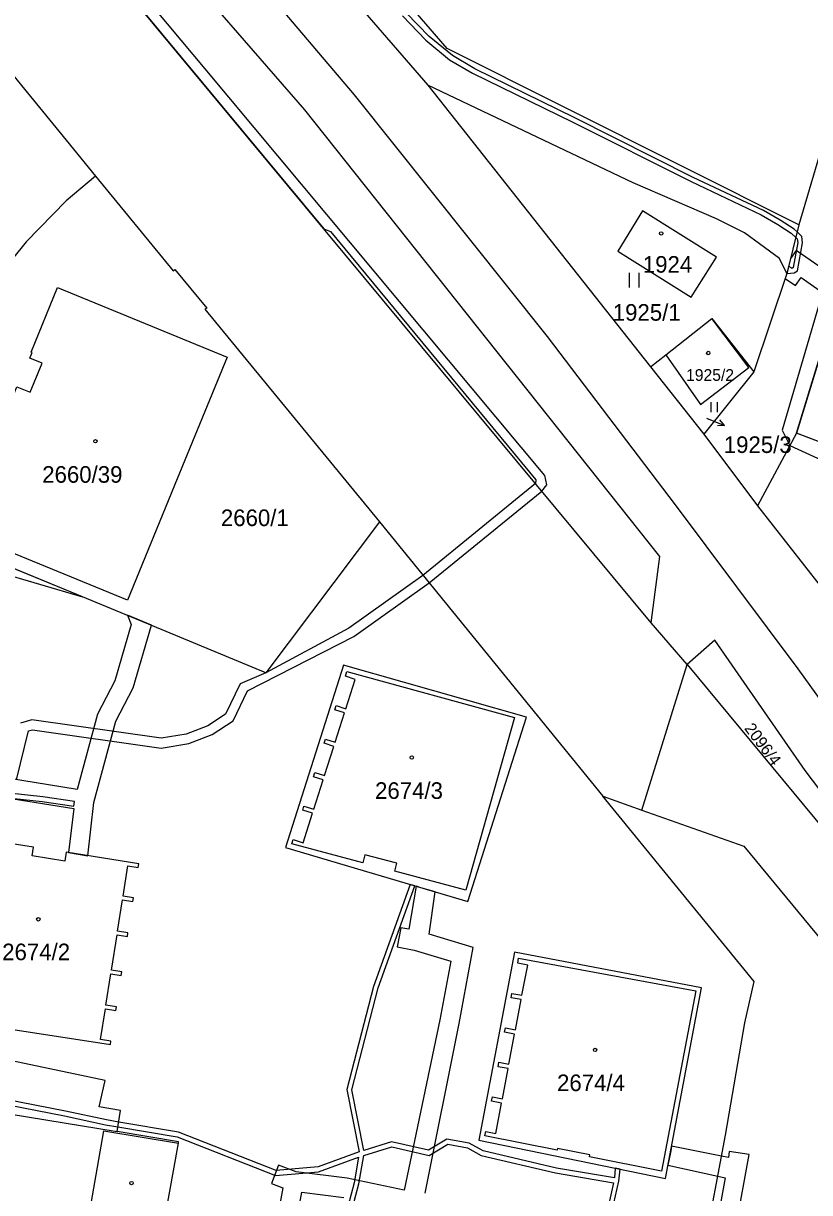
# Model space of a CAD drawing. Extents: x -756746 to -753363, y -1166406 to -1161727.
# Drawn here: x -755238.8 to -755158.3, y -1165086.9 to -1164967.1 of the extents above; entities that cross this region are included whole.
import ezdxf

# ---------------------------------------------------------------- set-up
doc = ezdxf.new("R2010")
doc.units = 0
for name, color, linetype in [('Hranice parcel', 7, 'Continuous'), ('Parcelní čísla', 7, 'Continuous'), ('Pop  PČ popisy', 7, 'Continuous'), ('Poz předměty', 7, 'Continuous'), ('Vnitřní kresba', 7, 'Continuous'), ('Věcná břemena k části', 7, 'Continuous'), ('Značky budov', 7, 'Continuous'), ('Značky kultur', 7, 'Continuous')]:
    doc.layers.add(name, color=color, linetype=linetype)

msp = doc.modelspace()

# ---------------------------------------------------------------- linework, layer by layer
at = {"layer": 'Hranice parcel'}
for p, q in [((-755232.98, -1164932.34), (-755197.4, -1164973.47)), ((-755150.26, -1164956.7), (-755159.39, -1164987.78)), ((-755197.4, -1164973.47), (-755174.57, -1165002.34)), ((-755159.39, -1164987.78), (-755160.61, -1164992.76)), ((-755160.61, -1164992.76), (-755163.99, -1165002.83)), ((-755154.6, -1164992.66), (-755159.64, -1165009.12)), ((-755173.02, -1165001.11), (-755168.29, -1164997.38)), ((-755168.29, -1164997.38), (-755163.99, -1165002.83)), ((-755174.57, -1165002.34), (-755173.02, -1165001.11)), ((-755174.57, -1165002.34), (-755169.12, -1165009.25)), ((-755163.99, -1165002.83), (-755169.12, -1165009.25)), ((-755169.12, -1165009.25), (-755163.64, -1165016.58)), ((-755159.64, -1165009.12), (-755163.64, -1165016.58)), ((-755146.3, -1165014.2), (-755159.64, -1165009.12)), ((-755163.64, -1165016.58), (-755133.33, -1165055.24)), ((-755202.36, -1165018.23), (-755179.46, -1165046.33)), ((-755170.82, -1165032.84), (-755174.51, -1165028.57)), ((-755175.48, -1165047.75), (-755170.82, -1165032.84)), ((-755170.82, -1165032.84), (-755144.59, -1165064.52)), ((-755179.46, -1165046.33), (-755175.48, -1165047.75)), ((-755225.33, -1165095.26), (-755222.94, -1165081.86))]:
    msp.add_line(p, q, dxfattribs=at)
for points in [[(-755174.51, -1165028.57), (-755173.62, -1165021.77), (-755210, -1164975.99), (-755240.66, -1164940.74), (-755264.36, -1164914.76), (-755305.85, -1164872.21)], [(-755174.51, -1165028.57), (-755239.27, -1164950.56), (-755255.53, -1164931.93), (-755293.61, -1164892.37), (-755304.73, -1164881.59)], [(-755159.39, -1164987.78), (-755195.43, -1164969.72), (-755209.4, -1164953.49)], [(-755243, -1164968.67), (-755235.2, -1164978.19), (-755231.43, -1164982.79)], [(-755160.61, -1164992.76), (-755161.38, -1164991.25), (-755164.97, -1164988.59), (-755167.82, -1164987.16), (-755176.37, -1164983.48), (-755197.4, -1164973.47)], [(-755231.43, -1164982.79), (-755234.45, -1164985.34), (-755238.55, -1164989.54), (-755241.2, -1164992.83), (-755243.99, -1164996.98), (-755245.9, -1165000.12), (-755247.84, -1165004.11), (-755249.68, -1165008.88), (-755251.02, -1165013.51)], [(-755231.43, -1164982.79), (-755223.48, -1164992.49), (-755223.3, -1164992.35), (-755220.03, -1164996.34), (-755220.24, -1164996.41), (-755202.36, -1165018.23)], [(-755175.39, -1164986.34), (-755177.93, -1164990.48), (-755170.41, -1164995.19), (-755167.83, -1164991.09), (-755175.39, -1164986.34)], [(-755228.17, -1165026.24), (-755245.56, -1165019.09), (-755242.86, -1165012.59), (-755242.76, -1165012.63), (-755242.52, -1165011.99), (-755241.25, -1165012.48), (-755240, -1165009.51), (-755241.38, -1165008.93), (-755239.5, -1165004.37), (-755238.12, -1165004.94), (-755236.91, -1165001.96), (-755238.17, -1165001.45), (-755237.91, -1165000.87), (-755238.01, -1165000.83), (-755235.33, -1164994.21), (-755217.94, -1165001.36), (-755223.06, -1165013.8), (-755228.17, -1165026.24)], [(-755173.02, -1165001.11), (-755169.47, -1165006.18), (-755164.5, -1165002.42), (-755168.29, -1164997.38)], [(-755228.38, -1165027.7), (-755232.75, -1165025.91), (-755252.01, -1165017.99)], [(-755202.36, -1165018.23), (-755214, -1165033.67), (-755228.38, -1165027.7)], [(-755144.59, -1165064.52), (-755150.03, -1165055.18), (-755158.73, -1165043.7), (-755167.99, -1165030.34), (-755170.82, -1165032.84)], [(-755187.29, -1165038.23), (-755206.02, -1165032.89), (-755211.96, -1165051.58), (-755193.28, -1165057.13), (-755187.29, -1165038.23)], [(-755195.18, -1165232.73), (-755194.72, -1165230.22), (-755190.08, -1165204.4), (-755187.88, -1165193.31), (-755185.72, -1165181.35), (-755183.4, -1165169.62), (-755181.35, -1165158.07), (-755178.5, -1165145.99), (-755176.9, -1165134.25), (-755174.82, -1165122.5), (-755171.34, -1165104.62), (-755169.11, -1165092.87), (-755166.91, -1165081.07), (-755164.91, -1165069.54), (-755163.98, -1165065.31), (-755179.46, -1165046.33)], [(-755175.48, -1165047.75), (-755165.04, -1165051.46), (-755150.8, -1165068.69)], [(-755240.75, -1165070.08), (-755229.91, -1165071.78), (-755229.85, -1165071.42), (-755230.91, -1165071.25), (-755230.42, -1165068.1), (-755229.36, -1165068.27), (-755229.3, -1165067.92), (-755230.36, -1165067.75), (-755229.85, -1165064.51), (-755228.79, -1165064.68), (-755228.74, -1165064.31), (-755229.79, -1165064.15), (-755229.23, -1165060.53), (-755228.17, -1165060.7), (-755228.11, -1165060.33), (-755229.17, -1165060.17), (-755228.66, -1165056.94), (-755227.6, -1165057.1), (-755227.54, -1165056.73), (-755228.6, -1165056.56), (-755228.11, -1165053.45), (-755227.05, -1165053.62), (-755227, -1165053.25), (-755234.44, -1165052.07), (-755234.59, -1165052.97), (-755237.93, -1165052.44), (-755237.78, -1165051.54), (-755245.22, -1165050.37)], [(-755192.17, -1165081.55), (-755173.06, -1165085.49), (-755169.36, -1165065.96), (-755188.53, -1165062.31), (-755192.17, -1165081.55)], [(-755229.21, -1165080.69), (-755228.87, -1165078.51), (-755231.05, -1165078.14), (-755230.44, -1165075.45), (-755241.34, -1165073.17), (-755240.75, -1165070.08)], [(-755257.09, -1165075.73), (-755243.85, -1165078.28), (-755229.21, -1165080.69)], [(-755232.91, -1165093.94), (-755230.59, -1165080.61), (-755222.94, -1165081.86)], [(-755222.94, -1165081.86), (-755222.92, -1165081.73), (-755229.21, -1165080.69)]]:
    msp.add_lwpolyline(points, dxfattribs=at)
at = {"layer": 'Pop  PČ popisy'}
for p, q in [((-755168.85, -1165007.58), (-755166.99, -1165008.33)), ((-755166.99, -1165008.33), (-755167.73, -1165008.39)), ((-755166.99, -1165008.33), (-755167.48, -1165007.77))]:
    msp.add_line(p, q, dxfattribs=at)
at = {"layer": 'Poz předměty'}
for p, q in [((-755204.91, -1164974.48), (-755230.66, -1164944.05)), ((-755185.13, -1164999.24), (-755204.91, -1164974.48)), ((-755172.01, -1165016.47), (-755185.13, -1164999.24)), ((-755159.45, -1165033.28), (-755172.01, -1165016.47)), ((-755146.57, -1165051.26), (-755159.45, -1165033.28))]:
    msp.add_line(p, q, dxfattribs=at)
at = {"layer": 'Vnitřní kresba'}
for p, q in [((-755205.84, -1165034.04), (-755205.68, -1165033.56)), ((-755204.84, -1165034.36), (-755205.84, -1165034.04)), ((-755205.79, -1165037.36), (-755204.84, -1165034.36)), ((-755205.68, -1165033.56), (-755188.52, -1165038.26)), ((-755206.93, -1165037.47), (-755206.79, -1165037.04)), ((-755206.79, -1165037.04), (-755205.79, -1165037.36)), ((-755205.93, -1165037.79), (-755206.93, -1165037.47)), ((-755206.89, -1165040.79), (-755205.93, -1165037.79)), ((-755188.52, -1165038.26), (-755193.5, -1165055.95)), ((-755208.02, -1165040.9), (-755207.89, -1165040.48)), ((-755207.89, -1165040.48), (-755206.89, -1165040.79)), ((-755207.02, -1165041.22), (-755208.02, -1165040.9)), ((-755207.99, -1165044.21), (-755207.02, -1165041.22)), ((-755209.12, -1165044.33), (-755208.98, -1165043.89)), ((-755208.98, -1165043.89), (-755207.99, -1165044.21)), ((-755208.12, -1165044.65), (-755209.12, -1165044.33)), ((-755209.08, -1165047.65), (-755208.12, -1165044.65)), ((-755210.21, -1165047.75), (-755210.08, -1165047.33)), ((-755209.21, -1165048.07), (-755210.21, -1165047.75)), ((-755210.08, -1165047.33), (-755209.08, -1165047.65)), ((-755210.18, -1165051.09), (-755209.21, -1165048.07)), ((-755211.32, -1165051.2), (-755211.18, -1165050.77)), ((-755204.04, -1165053.14), (-755211.32, -1165051.2)), ((-755211.18, -1165050.77), (-755210.18, -1165051.09)), ((-755203.83, -1165052.34), (-755204.04, -1165053.14)), ((-755200.57, -1165053.2), (-755203.83, -1165052.34)), ((-755200.78, -1165054.01), (-755200.57, -1165053.2)), ((-755193.5, -1165055.95), (-755200.78, -1165054.01)), ((-755188.19, -1165063.43), (-755188.1, -1165062.93)), ((-755187.16, -1165063.63), (-755188.19, -1165063.43)), ((-755188.1, -1165062.93), (-755169.94, -1165066.27)), ((-755187.75, -1165066.72), (-755187.16, -1165063.63)), ((-755188.86, -1165066.97), (-755188.78, -1165066.53)), ((-755187.83, -1165067.17), (-755188.86, -1165066.97)), ((-755188.78, -1165066.53), (-755187.75, -1165066.72)), ((-755169.94, -1165066.27), (-755173.46, -1165084.74)), ((-755188.41, -1165070.26), (-755187.83, -1165067.17)), ((-755189.54, -1165070.51), (-755189.45, -1165070.07)), ((-755188.5, -1165070.7), (-755189.54, -1165070.51)), ((-755189.45, -1165070.07), (-755188.41, -1165070.26)), ((-755189.08, -1165073.79), (-755188.5, -1165070.7)), ((-755190.2, -1165074.04), (-755190.11, -1165073.59)), ((-755189.17, -1165074.24), (-755190.2, -1165074.04)), ((-755190.11, -1165073.59), (-755189.08, -1165073.79)), ((-755189.75, -1165077.33), (-755189.17, -1165074.24)), ((-755190.87, -1165077.57), (-755190.78, -1165077.14)), ((-755189.84, -1165077.77), (-755190.87, -1165077.57)), ((-755190.78, -1165077.14), (-755189.75, -1165077.33)), ((-755190.42, -1165080.88), (-755189.84, -1165077.77)), ((-755191.54, -1165081.13), (-755191.46, -1165080.69)), ((-755184.16, -1165082.6), (-755191.54, -1165081.13)), ((-755191.46, -1165080.69), (-755190.42, -1165080.88)), ((-755184.12, -1165082.41), (-755184.16, -1165082.6)), ((-755180.81, -1165083.07), (-755184.12, -1165082.41)), ((-755180.85, -1165083.26), (-755180.81, -1165083.07)), ((-755173.46, -1165084.74), (-755180.85, -1165083.26))]:
    msp.add_line(p, q, dxfattribs=at)
at = {"layer": 'Věcná břemena k části'}
for points in [[(-755239.53, -1165044.65), (-755238.3, -1165039.63), (-755237.89, -1165039.52), (-755224.72, -1165041.39), (-755221.89, -1165040.94), (-755219.47, -1165040.02), (-755217.33, -1165038.61), (-755215.87, -1165035.54), (-755204.97, -1165029.98), (-755197.27, -1165024.48), (-755185.72, -1165015.07), (-755185.21, -1165014.43), (-755185.42, -1165013.47), (-755220.2, -1164971.82), (-755244.26, -1164943.04)], [(-755239.27, -1164950.56), (-755208.04, -1164988.18), (-755207.36, -1164988.47), (-755186.34, -1165013.91), (-755186.37, -1165014.29), (-755197.9, -1165023.7), (-755205.49, -1165029.12), (-755214, -1165033.67), (-755216.63, -1165034.8), (-755218.11, -1165037.93), (-755219.93, -1165039.12), (-755222.15, -1165039.96), (-755224.72, -1165040.37), (-755237.96, -1165038.5), (-755239.13, -1165038.83)], [(-755199.99, -1164966.39), (-755197.6, -1164968.85), (-755195.16, -1164970.87), (-755192.81, -1164972.24), (-755182.55, -1164977.26), (-755170.43, -1164983.36), (-755163.25, -1164986.77), (-755161.56, -1164987.74), (-755160.18, -1164988.63), (-755159.71, -1164989.09), (-755159.56, -1164989.23), (-755159.5, -1164989.61), (-755159.98, -1164992.17), (-755160.12, -1164992.25), (-755160.42, -1164991.98), (-755160.61, -1164992.76), (-755159.86, -1164992.69), (-755159.52, -1164992.49), (-755159, -1164989.63), (-755159.08, -1164988.99), (-755159.57, -1164988.51), (-755159.86, -1164988.23), (-755161.3, -1164987.32), (-755163.01, -1164986.33), (-755170.21, -1164982.92), (-755182.33, -1164976.82), (-755192.57, -1164971.8), (-755194.88, -1164970.45), (-755197.26, -1164968.49), (-755199.61, -1164966.05)], [(-755146.3, -1165014.2), (-755159.64, -1165009.12), (-755154.92, -1164993.71), (-755159.66, -1164990.4), (-755160.23, -1164991.22), (-755160.61, -1164992.76), (-755160.78, -1164993.27), (-755159.73, -1164994), (-755159.16, -1164993.18), (-755156.97, -1164994.71), (-755161.1, -1165008.83), (-755160.32, -1165010.38), (-755153.75, -1165013.4)], [(-755245.23, -1165045.97), (-755236.9, -1165046.88), (-755233.66, -1165047.35), (-755233.58, -1165046.86), (-755236.84, -1165046.38), (-755245.64, -1165045.42)], [(-755178.67, -1165089.51), (-755177.82, -1165085.77), (-755177.7, -1165084.53), (-755178.19, -1165084.43), (-755178.29, -1165085.44), (-755184.23, -1165084.43), (-755191.74, -1165082.65), (-755193.15, -1165081.89), (-755195.45, -1165081.46), (-755197.32, -1165082.59), (-755201.11, -1165081.74), (-755203.96, -1165082.61), (-755205.17, -1165076.41), (-755202.48, -1165065.97), (-755198.74, -1165055.51), (-755199.22, -1165055.36), (-755202.96, -1165065.83), (-755205.68, -1165076.39), (-755204.44, -1165082.77), (-755208.64, -1165084.31), (-755212.92, -1165084.67), (-755222.93, -1165080.76), (-755229.06, -1165079.71), (-755230.32, -1165079.49), (-755234.52, -1165078.59), (-755248.69, -1165075.82)], [(-755197.66, -1165086.98), (-755194.2, -1165069.63), (-755192.74, -1165061.81), (-755197.25, -1165060.47), (-755196.65, -1165056.13), (-755197.13, -1165055.99), (-755198.1, -1165055.7), (-755198.6, -1165055.55), (-755199.33, -1165059.96), (-755200.17, -1165059.81), (-755200.53, -1165061.77), (-755198.8, -1165062.09), (-755195.04, -1165063.21), (-755196.16, -1165069.25), (-755199.81, -1165086.68), (-755205.67, -1165085.47), (-755210.87, -1165084.82), (-755212.7, -1165084.14), (-755213.4, -1165086.01), (-755212.24, -1165086.44), (-755213.13, -1165091.29)], [(-755248.97, -1165076.28), (-755234.62, -1165079.08), (-755230.42, -1165079.98), (-755229.13, -1165080.2), (-755223.07, -1165081.24), (-755212.99, -1165085.18), (-755208.59, -1165084.82), (-755204.48, -1165083.32), (-755204.95, -1165085.94), (-755205.57, -1165088.27)], [(-755205.08, -1165088.36), (-755204.46, -1165086.05), (-755203.94, -1165083.13), (-755201.09, -1165082.26), (-755197.24, -1165083.12), (-755195.35, -1165081.98), (-755193.32, -1165082.36), (-755191.92, -1165083.12), (-755184.33, -1165084.92), (-755178.37, -1165085.93), (-755179.17, -1165089.49)], [(-755165.81, -1165090.34), (-755164.48, -1165083.04), (-755166.52, -1165082.74), (-755166.61, -1165083.34), (-755167.31, -1165083.2), (-755172.43, -1165082.18), (-755172.52, -1165082.66), (-755172.71, -1165083.64), (-755172.8, -1165084.14), (-755167.69, -1165085.25), (-755166.94, -1165085.41), (-755167.77, -1165089.94)], [(-755210.81, -1165089.73), (-755210.3, -1165086.91), (-755205.99, -1165087.45)]]:
    msp.add_lwpolyline(points, dxfattribs=at)
for points in [[(-755241.6, -1165023.29), (-755232.75, -1165025.91), (-755246.84, -1165020.12), (-755247.96, -1165019.66), (-755247.15, -1165021.09)], [(-755233.67, -1165047.6), (-755234.19, -1165052.11), (-755232.22, -1165052.42), (-755231.59, -1165046.98), (-755229.36, -1165038.65), (-755227.58, -1165035.23), (-755225.71, -1165028.81), (-755226.52, -1165028.47), (-755227.18, -1165028.2), (-755228.17, -1165027.79), (-755227.77, -1165028.73), (-755229.44, -1165034.49), (-755231.24, -1165037.93), (-755233.3, -1165045.63), (-755241.96, -1165044.25), (-755249.03, -1165043.19), (-755249.33, -1165045.17), (-755242.26, -1165046.23)]]:
    msp.add_lwpolyline(points, close=True, dxfattribs=at)
at = {"layer": 'Značky budov'}
for centre in [(-755173.49, -1164988.67), (-755168.67, -1165000.92), (-755231.44, -1165009.96), (-755199.04, -1165042.36), (-755237.29, -1165058.94), (-755180.26, -1165072.32), (-755227.75, -1165085.96)]:
    msp.add_circle(centre, 0.175, dxfattribs=at)
at = {"layer": 'Značky kultur'}
for p, q in [((-755176.73, -1164994.21), (-755176.73, -1164992.71)), ((-755175.73, -1164994.21), (-755175.73, -1164992.71)), ((-755168.38, -1165006.97), (-755168.38, -1165005.97)), ((-755167.71, -1165006.97), (-755167.71, -1165005.97))]:
    msp.add_line(p, q, dxfattribs=at)

# ---------------------------------------------------------------- texts
at = {"layer": 'Parcelní čísla'}
for s, height, p in [('1924', 1.7, (-755175.37, -1164992.69)), ('1925/1', 1.7, (-755178.45, -1164997.61)), ('1925/2', 1.2, (-755170.94, -1165003.77)), ('1925/3', 1.7, (-755167.08, -1165011.16)), ('2660/39', 1.7, (-755236.89, -1165014.21)), ('2660/1', 1.7, (-755218.59, -1165018.65)), ('2674/3', 1.7, (-755202.8, -1165046.6)), ('2674/2', 1.7, (-755240.99, -1165063.13)), ('2674/4', 1.7, (-755184.16, -1165076.54))]:
    msp.add_text(s, height=height, dxfattribs=at).set_placement(p)
msp.add_text('2096/4', height=1.2, rotation=307, dxfattribs=at).set_placement((-755165.03, -1165039.39))

doc.saveas('drawing.dxf')
